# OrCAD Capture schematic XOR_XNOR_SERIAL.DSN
size A
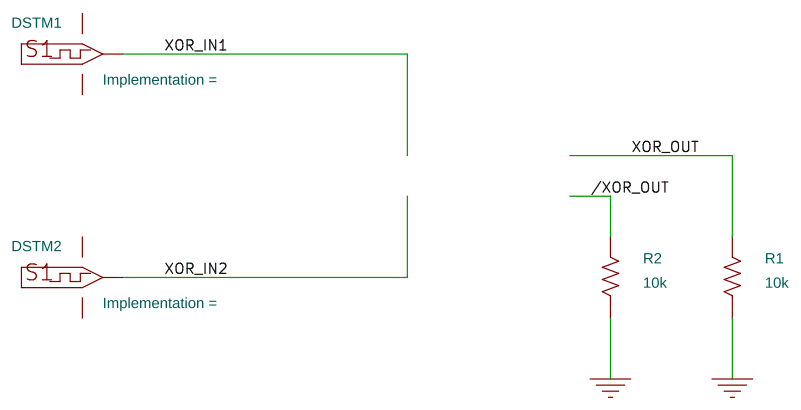
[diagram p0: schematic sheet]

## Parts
DSTM1  DigStim1
DSTM2  DigStim1
R1  10k  [AXRC05]
R2  10k  [AXRC05]

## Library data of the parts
DSTM1 DSTM2 = DigStim1
R1 R2 = R

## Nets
GND: DSTM1.3(GND) DSTM2.3(GND)
VCC: DSTM1.2(VCC) DSTM2.2(VCC)
0: R1.1 R2.1
/XOR_OUT: R2.2
XOR_IN1: DSTM1.OUT
XOR_IN2: DSTM2.OUT
XOR_OUT: R1.2
